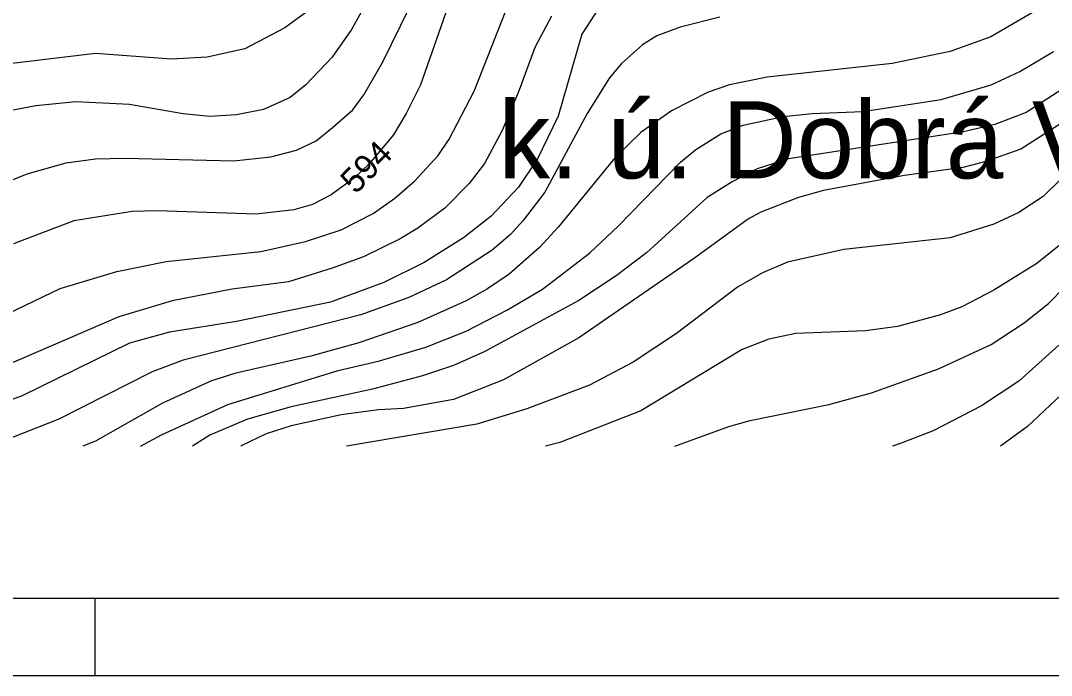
# Model space of a CAD drawing. Extents: x -709418 to -703832, y -1161719 to -1157826.
# Drawn here: x -709106.3 to -708772.4, y -1161718.9 to -1161506.7 of the extents above; entities that cross this region are included whole.
import ezdxf

# ---------------------------------------------------------------- set-up
doc = ezdxf.new("R2010")
doc.units = 0
for name, color, linetype in [('104_název KÚ', 7, 'Continuous'), ('120_vrstevnice hlavní', 7, 'Continuous'), ('121_vrstevnice hlavní_popis', 7, 'Continuous'), ('122_vrstevnice základní', 7, 'Continuous'), ('800_mřížka', 7, 'Continuous')]:
    doc.layers.add(name, color=color, linetype=linetype)

msp = doc.modelspace()

# ---------------------------------------------------------------- linework, layer by layer
at = {"layer": '120_vrstevnice hlavní'}
for points in [[(-708993.97, -1161500.34), (-708999.18, -1161509.6), (-709005.39, -1161518.57), (-709013.93, -1161527.53), (-709018.99, -1161531.58), (-709027.67, -1161535.49)], [(-708918.95, -1161502.49), (-708924.5, -1161511.06), (-708932.2, -1161537.66), (-708938.86, -1161551.55), (-708945.08, -1161560.66), (-708953.9, -1161570.06), (-708962.87, -1161577.15), (-708975.6, -1161585.1), (-708988.62, -1161591.61), (-709005.97, -1161597.98), (-709036.35, -1161604.2), (-709058.05, -1161607.67), (-709071.06, -1161611.28), (-709105.78, -1161628.35), (-709114.46, -1161631.39)], [(-708663.46, -1161522.33), (-708678.64, -1161535.49), (-708697.88, -1161551.11), (-708726.38, -1161576.57), (-708749.37, -1161601.74), (-708767.31, -1161626.18), (-708780.18, -1161638.19), (-708788.14, -1161644.12), (-708788.92, -1161644.59)], [(-709027.67, -1161535.49), (-709036.35, -1161537.23), (-709045.03, -1161537.8), (-709053.71, -1161536.94), (-709071.06, -1161533.9), (-709088.42, -1161533.03), (-709101.44, -1161534.33), (-709109.97, -1161535.92)], [(-708767.6, -1161538.96), (-708782.35, -1161548.36), (-708793.64, -1161552.41), (-708801.16, -1161554.29), (-708819.96, -1161556.9), (-708846.29, -1161561.81), (-708854.39, -1161563.99), (-708866.54, -1161568.76), (-708870.59, -1161570.93), (-708888.38, -1161583.95), (-708925.55, -1161609.55), (-708949.85, -1161623.15), (-708966.05, -1161629.51), (-708982.25, -1161632.4), (-708990.35, -1161632.84), (-709002.5, -1161634.43), (-709018.7, -1161638.04), (-709026.8, -1161640.65), (-709034.9, -1161644.55), (-709034.97, -1161644.59)]]:
    msp.add_lwpolyline(points, dxfattribs=at)
at = {"layer": '122_vrstevnice základní'}
for points in [[(-708625.56, -1161113.71), (-708667.8, -1161172.87), (-708684.86, -1161205.27), (-708693.83, -1161226.1), (-708698.32, -1161239.98), (-708700.63, -1161250.98), (-708702.8, -1161267.18), (-708703.23, -1161285.4), (-708702.22, -1161307.68), (-708697.16, -1161336.03), (-708693.25, -1161365.53), (-708692.24, -1161384.05), (-708692.38, -1161395.62), (-708693.69, -1161407.19), (-708698.46, -1161425.71), (-708701.5, -1161432.65), (-708707.86, -1161443.06), (-708714.52, -1161452.32), (-708730.14, -1161470.11), (-708742.43, -1161481.39), (-708750.68, -1161487.76), (-708792.02, -1161511.98)], [(-708894.45, -1161644.59), (-708876.95, -1161638.19), (-708870.01, -1161636.31), (-708844.55, -1161631.1), (-708830.66, -1161627.34), (-708808.97, -1161619.53), (-708791.9, -1161611.72), (-708781.2, -1161604.63), (-708773.39, -1161598.41), (-708752.85, -1161577.44), (-708722.76, -1161548.51), (-708689.2, -1161519.15), (-708652.32, -1161492.96), (-708639.59, -1161482.98), (-708613.99, -1161467.94), (-708601.11, -1161459.26), (-708590.99, -1161449.72), (-708586.22, -1161443.35), (-708584.05, -1161439.45), (-708581.88, -1161433.52), (-708580.86, -1161424.26), (-708581.73, -1161412.69)], [(-708920.06, -1161455.5), (-708928.16, -1161459.12), (-708940.31, -1161465.63), (-708951.44, -1161474.45), (-708960.12, -1161485.88), (-708963.74, -1161492.82), (-708968.66, -1161504.39), (-708976.76, -1161527.54), (-708981.38, -1161536.79), (-708985.58, -1161543.74), (-708993.39, -1161553.14), (-708998.16, -1161557.62), (-709005.68, -1161563.12), (-709011.76, -1161566.3), (-709017.83, -1161568.04), (-709029.98, -1161569.48), (-709062.1, -1161568.32), (-709070.2, -1161568.61), (-709089.1, -1161571.55), (-709108.67, -1161579.03)], [(-709115.47, -1161560.95), (-709104.19, -1161556.32), (-709091.6, -1161552.85), (-709082.06, -1161551.55), (-709072.51, -1161551.26), (-709037.22, -1161552.12), (-709025.25, -1161550.86), (-709016.93, -1161548.66), (-709010.63, -1161545.72), (-709005.34, -1161541.31), (-708998.74, -1161535.64), (-708995.12, -1161530.72), (-708989.05, -1161520.3), (-708971.26, -1161483.85)], [(-709127.47, -1161609.84), (-709093.48, -1161593.49), (-709075.11, -1161588), (-709059.2, -1161584.81), (-709028.54, -1161581.49), (-709014.07, -1161578.31), (-709002.5, -1161574.54), (-708992.09, -1161569.19), (-708985.14, -1161564.27), (-708978.78, -1161558.78), (-708971.11, -1161550.39), (-708967.5, -1161545.18), (-708959.4, -1161529.56), (-708949.13, -1161503.52)], [(-709013.21, -1161503.52), (-709020.73, -1161509.02)], [(-708934.37, -1161505.26), (-708939.73, -1161515.39), (-708944.79, -1161529.27), (-708950.29, -1161542.29), (-708956.07, -1161552.99), (-708960.99, -1161559.5), (-708968.94, -1161567.46), (-708977.62, -1161573.97), (-708983.41, -1161577.44), (-708995.27, -1161583.22), (-709005.4, -1161586.98), (-709019.57, -1161591.32), (-709037.8, -1161593.78), (-709057.18, -1161597.54), (-709074.54, -1161602.75), (-709117.93, -1161621.41)], [(-708879.84, -1161505.55), (-708892.72, -1161508.88), (-708900.24, -1161511.62), (-708904.87, -1161514.52), (-708911.67, -1161520.59), (-708915.57, -1161525.22), (-708922.8, -1161536.79), (-708936.54, -1161562.25), (-708943.49, -1161571.51), (-708947.68, -1161575.99), (-708953.61, -1161581.05), (-708968.37, -1161590.74), (-708980.52, -1161596.39), (-708996.14, -1161602.03), (-709053.71, -1161616.78), (-709063.69, -1161620.54), (-709093.92, -1161635.87), (-709109.25, -1161641.95)], [(-709020.73, -1161509.02), (-709033.74, -1161515.82), (-709045.9, -1161518.57), (-709057.47, -1161519.15), (-709082.06, -1161517.41), (-709109.05, -1161520.64)], [(-708792.02, -1161511.98), (-708805.21, -1161516.69), (-708824.01, -1161520.59), (-708864.51, -1161525.08), (-708876.66, -1161527.53), (-708883.6, -1161529.85), (-708895.47, -1161535.92), (-708905.45, -1161543.01), (-708913.69, -1161551.11), (-708932.06, -1161573.53), (-708938.28, -1161580.19), (-708948.12, -1161588.86), (-708955.06, -1161593.64), (-708962, -1161597.54), (-708977.62, -1161604.49), (-708996.72, -1161611.14), (-709012.34, -1161615.48), (-709036.64, -1161620.98), (-709044.45, -1161623.43), (-709060.36, -1161630.67), (-709082.06, -1161642.96), (-709086.19, -1161644.59)], [(-709067.45, -1161644.59), (-709060.65, -1161640.94), (-709039.24, -1161631.1), (-709003.51, -1161620.11), (-708990.06, -1161616.93), (-708975.02, -1161612.58), (-708962, -1161607.38), (-708948.84, -1161600.58), (-708937.27, -1161593.78), (-708922.08, -1161582.07), (-708912.68, -1161573.24), (-708892.57, -1161552.56), (-708887.65, -1161548.51), (-708879.55, -1161543.45), (-708872.32, -1161540.55), (-708859.3, -1161537.8), (-708849.76, -1161536.79), (-708833.56, -1161536.21), (-708808.1, -1161532.31), (-708791.9, -1161527.53), (-708782.64, -1161523.2), (-708771.79, -1161516.69)], [(-708768.76, -1161528.84), (-708780.62, -1161536.5), (-708790.74, -1161540.41), (-708800.87, -1161542.72), (-708857.57, -1161551.55), (-708867.69, -1161554.73), (-708875.79, -1161558.92), (-708883.89, -1161563.99), (-708903.57, -1161581.92), (-708913.4, -1161589.44), (-708925.55, -1161597.4), (-708955.93, -1161613.89), (-708966.05, -1161618.52), (-708976.18, -1161621.84), (-708992.38, -1161626.18), (-709018.7, -1161631.82), (-709032.88, -1161635.87), (-709045.03, -1161641.08), (-709050.59, -1161644.59)], [(-708769.05, -1161557.77), (-708775.12, -1161563.7), (-708782.93, -1161568.9), (-708791.03, -1161572.66), (-708805.21, -1161577.15), (-708839.63, -1161580.91), (-708857.86, -1161584.96), (-708865.96, -1161588.43), (-708874.06, -1161593.06), (-708893.87, -1161608.1), (-708907.9, -1161617.36), (-708922.08, -1161624.88), (-708942.33, -1161632.55), (-708958.53, -1161637.46), (-709000.76, -1161644.59)], [(-708763.41, -1161574.4), (-708777.15, -1161585.39), (-708791.03, -1161594.07), (-708801.45, -1161599.42), (-708808.39, -1161602.03), (-708822.28, -1161605.79), (-708832.69, -1161607.23), (-708855.25, -1161608.1), (-708863.93, -1161609.98), (-708872.61, -1161613.31), (-708905.45, -1161633.12), (-708931.63, -1161643.4), (-708936.26, -1161644.59)], [(-708770.06, -1161611.86), (-708782.93, -1161623.58), (-708795.08, -1161631.53), (-708810.7, -1161639.63), (-708821.12, -1161643.68), (-708823.94, -1161644.59)]]:
    msp.add_lwpolyline(points, dxfattribs=at)
at = {"layer": '800_mřížka'}
for points in [[(-703832.2, -1161718.9), (-703832.2, -1157825.62), (-709417.73, -1157825.62), (-709417.73, -1161718.9)], [(-703857.2, -1161693.9), (-703857.2, -1157850.62), (-709392.73, -1157850.62), (-709392.73, -1161693.9)]]:
    msp.add_lwpolyline(points, close=True, dxfattribs=at)
msp.add_lwpolyline([(-709082.2, -1161718.9), (-709082.2, -1161718.9), (-709082.2, -1161693.9)], dxfattribs=at)

# ---------------------------------------------------------------- texts
at = {"layer": '104_název KÚ'}
msp.add_text('k. ú. Dobrá Voda u Číměře', height=25, dxfattribs=at).set_placement((-708951.53, -1161557.84))
at = {"layer": '121_vrstevnice hlavní_popis'}
msp.add_text('594', height=8, rotation=45.2779, dxfattribs=at).set_placement((-708997.8, -1161563.22))

doc.saveas('drawing.dxf')
